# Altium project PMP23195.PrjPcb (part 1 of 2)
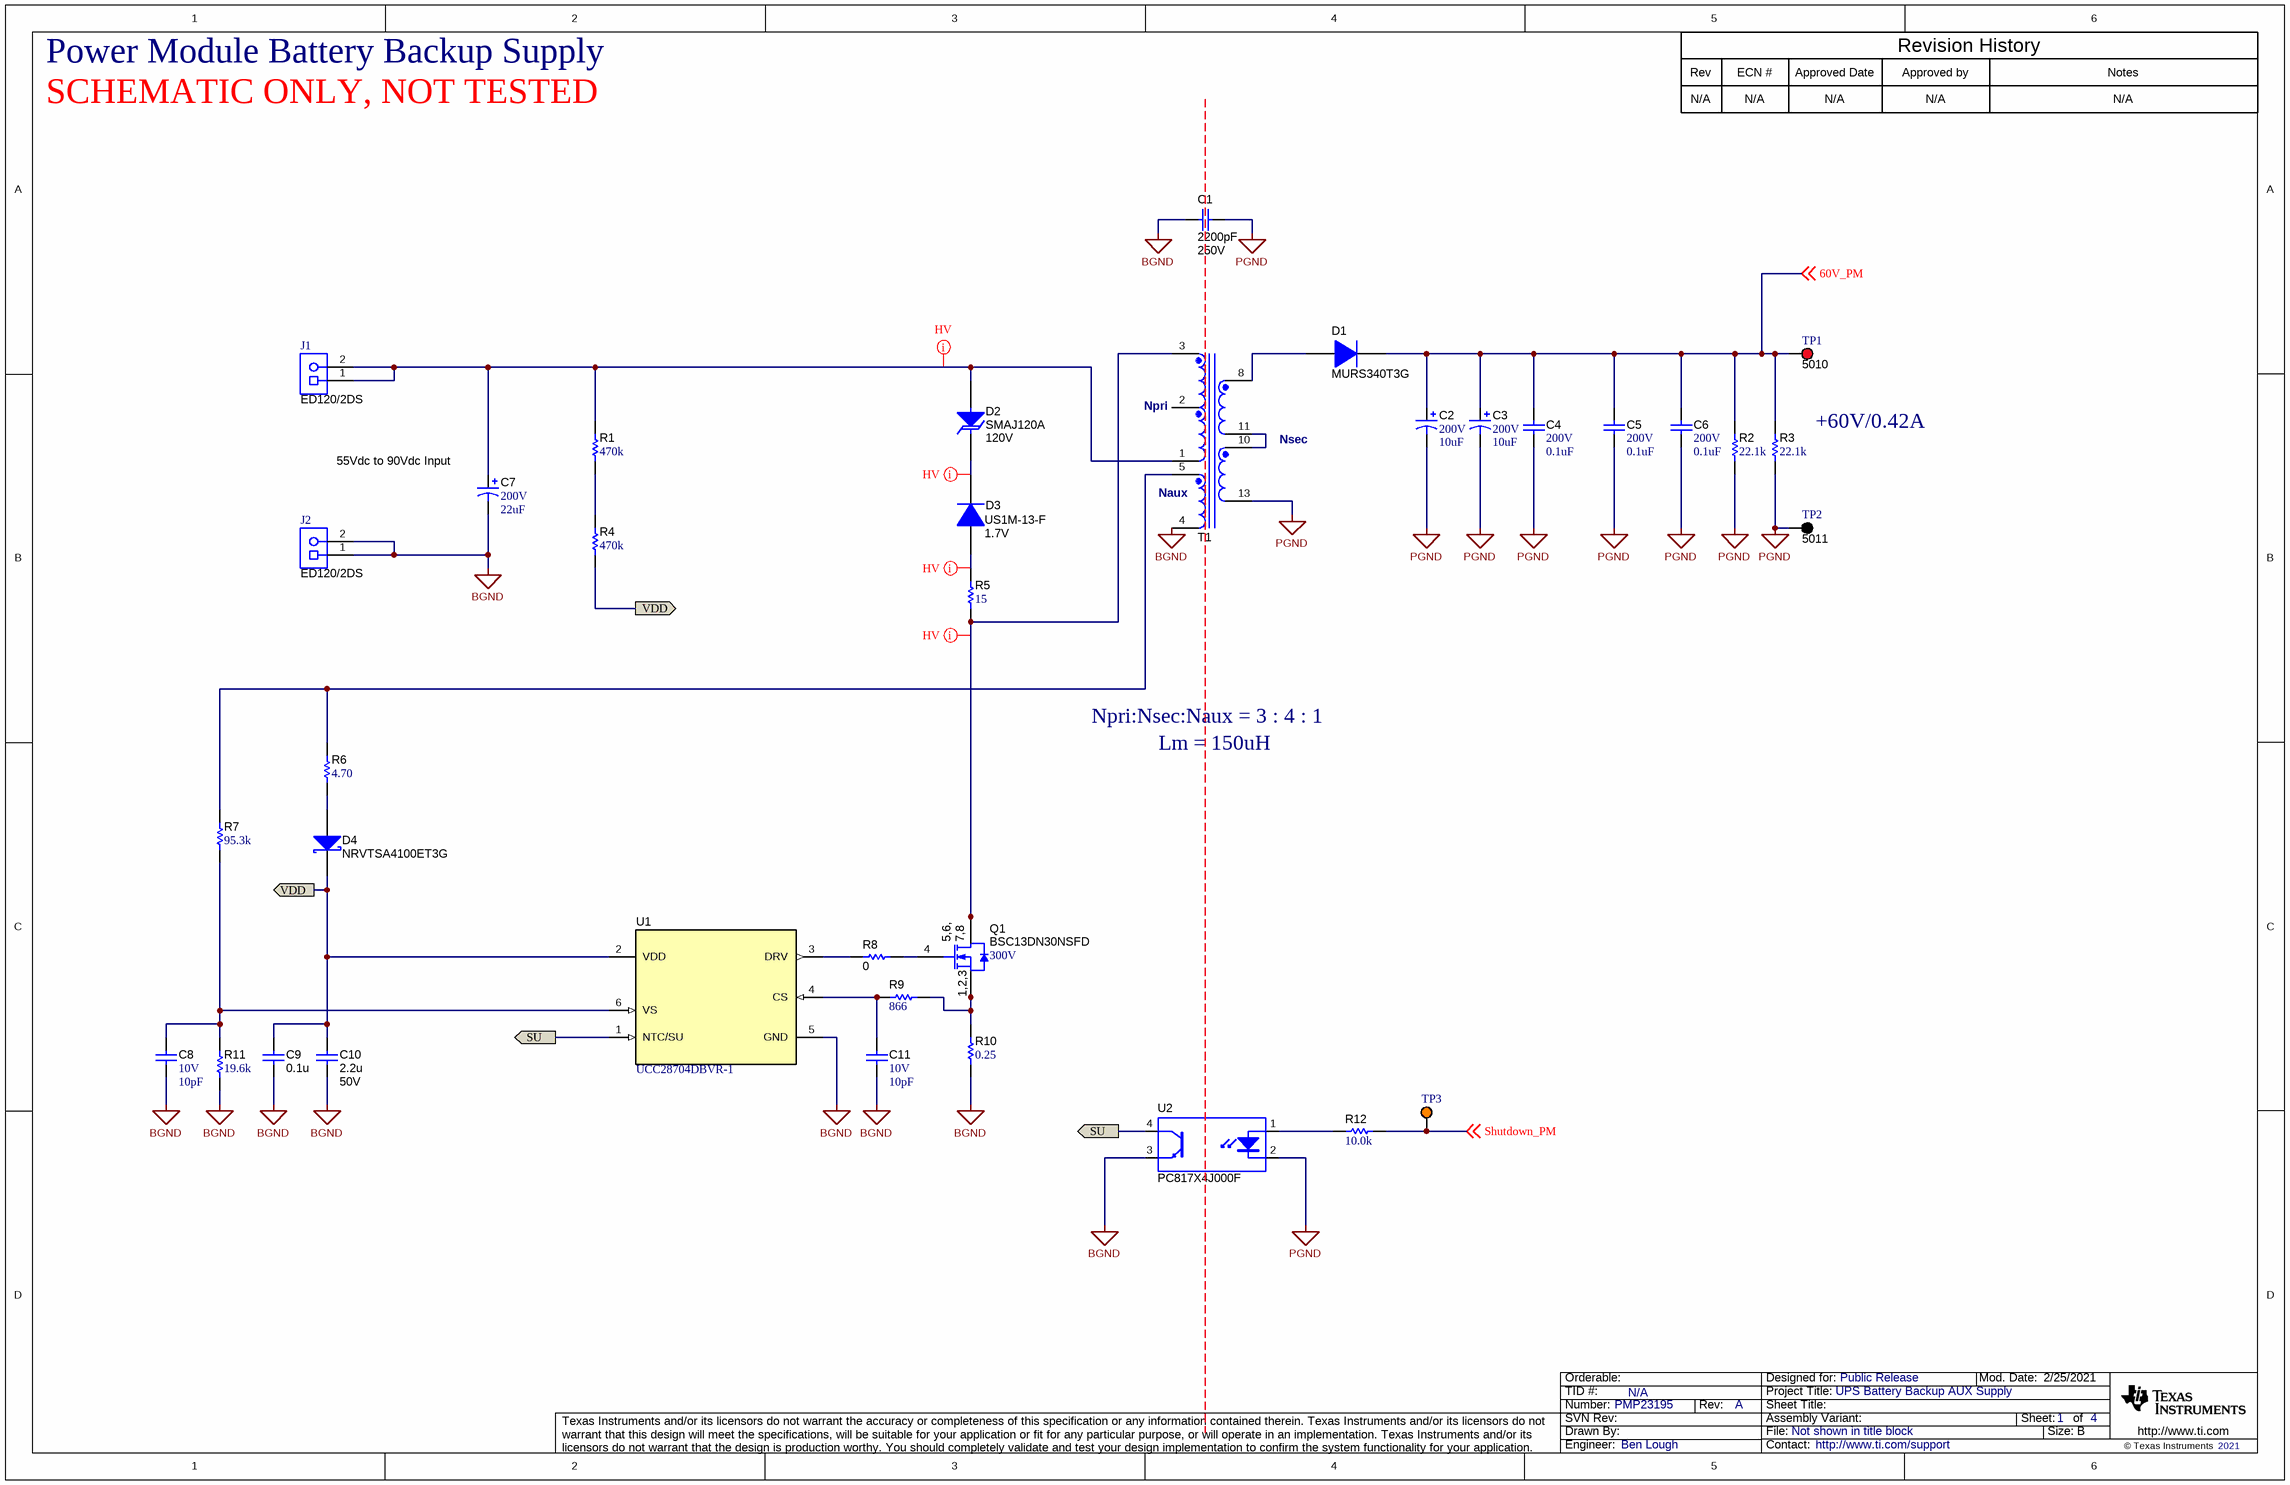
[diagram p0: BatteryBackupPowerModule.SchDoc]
CopyrightYear: 2021; PCB_Layout: N/A; PCB_Rev: A; PRJ_Customer: Public Release; PRJ_Engineer: Ben Lough; PRJ_Number: PMP23195; PRJ_Title: UPS Battery Backup AUX Supply; SCH_Rev: A; TechSupport: http://www.ti.com/support; TID: N/A
4 sheets, 246 parts. Net scope: flat (ports and power ports of the same name join across sheets).
Board file: PMP23195.PcbDoc
Sheets:
  BatteryBackupPowerModule.SchDoc
  PowerModule_ZVS_Flyback.SchDoc
  SystemAUX_ZVSFlyback.SchDoc
  BatteryBackupSystemAUX.SchDoc

## Sheet BatteryBackupPowerModule.SchDoc
size 431 x 279 mm; Date: Not shown in title block; ApprovedBy: Not shown in title block; CheckedBy: Not shown in title block; Author: Not shown in title block; CompanyName: Not shown in title block; Engineer: Not shown in title block; Organization: Not shown in title block; Address1: Not shown in title block; Address2: Not shown in title block; Address3: Not shown in title block; Address4: Not shown in title block; DocumentNumber: 1; Revision: Use project parameter SCH_Rev; SheetNumber: 1; SheetTotal: 4; PageSetup: Record=PageOptions¦CenterHorizontal=True¦CenterVertical=True¦PrintScale=1.00¦XCorrection=1.00¦YCorrection=1.00¦PrintKind=0¦BorderSize=5000000¦LeftOffset=0¦BottomOffset=0¦Orientation=2¦PaperLength=1000¦PaperWidth=1000¦Scale=100¦PaperSource=15¦PrintQuality=600¦MediaType=1¦DitherType=10¦PaperKind=Letter¦PrintScaleMode=1

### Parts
C1  ValueDisplayed: 2200pF  Value2: 250V  [CAPRD750W60D1050H1450]  (hidden comment: CS11-E2GA222MYNS)
C2  VDC_V: 200V  ValueDisplayed: 10uF  [VK_800X1150]  (hidden comment: UVK2D100MPD)
C3  VDC_V: 200V  ValueDisplayed: 10uF  [VK_800X1150]  (hidden comment: UVK2D100MPD)
C4  VDC_V: 200V  ValueDisplayed: 0.1uF  [1206]  (hidden comment: C1206C104K2RACTU)
C5  VDC_V: 200V  ValueDisplayed: 0.1uF  [1206]  (hidden comment: C1206C104K2RACTU)
C6  VDC_V: 200V  ValueDisplayed: 0.1uF  [1206]  (hidden comment: C1206C104K2RACTU)
C7  VDC_V: 200V  ValueDisplayed: 22uF  [UPW_1000x2000]  (hidden comment: UPW2D220MPD1TD)
C8  VDC_V: 10V  ValueDisplayed: 10pF  [0402]  (hidden comment: C0402C100C8GACTU)
C9  ValueDisplayed: 0.1u  [0603]  (hidden comment: 06035C104KAT2A)
C10  ValueDisplayed: 2.2u  Value2: 50V  [1206]  (hidden comment: GRM31CR61H225KA88L)
C11  VDC_V: 10V  ValueDisplayed: 10pF  [0402]  (hidden comment: C0402C100C8GACTU)
D1  MURS340T3G  [SMC]
D2  SMAJ120A  value 120V  [SMA]
D3  US1M-13-F  value 1.7V  [SMA]
D4  NRVTSA4100ET3G  [SMA]
J1  ED120/2DS  [On-Shore_ED120_2DS]
J2  ED120/2DS  [On-Shore_ED120_2DS]
Q1  BSC13DN30NSFD  value 300V  [PG-TDSON-8]
R1  ValueDisplayed: 470k  [1206]  (hidden comment: RC1206FR-07470KL)
R2  ValueDisplayed: 22.1k  [1206]  (hidden comment: RC1206FR-0722K1L)
R3  ValueDisplayed: 22.1k  [1206]  (hidden comment: RC1206FR-0722K1L)
R4  ValueDisplayed: 470k  [1206]  (hidden comment: RC1206FR-07470KL)
R5  ValueDisplayed: 15  [1206]  (hidden comment: CRCW120615R0JNEA)
R6  ValueDisplayed: 4.70  [1206]  (hidden comment: RC1206FR-074R7L)
R7  ValueDisplayed: 95.3k  [0603]  (hidden comment: RC0603FR-0795K3L)
R8  value 0  [0603]  (hidden comment: CRCW06030000Z0EA)
R9  ValueDisplayed: 866  [0603]  (hidden comment: RC0603FR-07866RL)
R10  ValueDisplayed: 0.25  [1206]  (hidden comment: CSR1206FKR250)
R11  ValueDisplayed: 19.6k  [0603]  (hidden comment: RC0603FR-0719K6L)
R12  ValueDisplayed: 10.0k  [0603]  (hidden comment: M55342K12B10E0T)
T1  750314727  [WURTH_750314727]  (value not drawn)
TP1  5010  [Keystone5010]
TP2  5011  [Keystone5011]
TP3  5013  [Keystone5013]  (value not drawn)
U1  UCC28704DBVR-1  [DBV0006A_N]
U2  PC817X4J000F  [DIP762W60P254L460H350Q4B]

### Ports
SU (out), VDD (out)

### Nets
BGND: C1.2 C7.2(-) C8.2 C9.2 C10.2 C11.2 J2.1 J2.2 R10.1 R11.1 T1.4 U1.5(GND) U2.3(E)
PGND: C1.1 C2.2(-) C3.2(-) C4.2 C5.2 C6.2 R2.1 R3.1 T1.13 TP2.1 U2.2(K)
60V_PM: C2.1(+) C3.1(+) C4.1 C5.1 C6.1 D1.1(K) R2.2 R3.2 TP1.1 ; off-sheet 60V_PM
Shutdown_PM: R12.2 TP3.1 ; off-sheet Shutdown_PM
SU: U1.1(NTC/SU) U2.4(C) ; port SU
VDD: C9.1 C10.1 D4.1(K) R4.1 U1.2(VDD) ; port VDD
NetC7_1: C7.1(+) D2.2(A) J1.1 J1.2 R1.2 T1.1
NetC8_1: C8.1 R7.1 R11.2 U1.6(VS)
NetC11_1: C11.1 R9.1 U1.4(CS)
NetD1_2: D1.2(A) T1.8
NetD2_1: D2.1(K) D3.1(K)
NetD3_2: D3.2(A) R5.2
NetD4_2: D4.2(A) R6.1
NetQ1_1: Q1.1(S) Q1.2(S) Q1.3(S) R9.2 R10.2
NetQ1_4: Q1.4(G) R8.2
NetQ1_5: Q1.5(D) Q1.6(D) Q1.7(D) Q1.8(D) Q1.9(D) R5.1 T1.3
NetR1_1: R1.1 R4.2
NetR6_2: R6.2 R7.2 T1.5
NetR8_1: R8.1 U1.3(DRV)
NetR12_1: R12.1 U2.1(A)
NetT1_10: T1.10 T1.11

Not connected (* = marked no-connect by the designer): T1 2

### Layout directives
net class HV: NetC7_1, NetD2_1, NetD3_2, NetQ1_5

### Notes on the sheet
- Power Module Battery Backup Supply
- Rev
- N/A
- ECN #
- Approved Date
- Approved by
- Revision History
- Notes
- SCHEMATIC ONLY, NOT TESTED
- (near T1) Npri
- +60V/0.42A
- (near C7) 55Vdc to 90Vdc Input
- (near T1) Naux
- Nsec
- Npri:Nsec:Naux = 3 : 4 : 1
- Lm = 150uH

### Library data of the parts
C1 = CS11-E2GA222MYNS: CAP, CERM, 2200pF, 250V, +/-20%, E, Radial Disc D10.5x7mm; Manufacturer: TDK; Polarized: N; CompType: Capacitor; U/M: EA; Cap_F: 0.0000000022; Tolerance_%: 20; Value1: Unknown; VDC_V: 250; TaMin_C: -25; TaMax_C: 105; Cap_Case: Disc, 10.5x7mm
C2 C3 = CMP-0064891-1: CAP, AL, 10 uF, 200 V, +/- 20%, TH; Manufacturer: Nichicon; TaMin_C: -40°C; Polarized: Y; SizeAreaWB_mm2: 100; Value1: Unknown; U/M: EA; Value: 10uF; TaMax_C: 85°C; SizeZ_mm: 13; SizeX_mm: 8; Cap_Case: 8x11.5mm; SizeArea_mm2: 64; CompType: Capacitor; AEC Qualified: N; Cap_F: 10µF; IRMS_A: 80mA; AEC Category: Q200
C4-C6 = CMP-0008585-2: CAP, CERM, 0.1 uF, 200 V, +/- 10%, X7R, 1206; Manufacturer: Kemet; TaMin_C: -55°C; Polarized: N; SizeAreaWB_mm2: 10.92; Value1: Unknown; U/M: EA; Value: 0.1uF; TaMax_C: 125°C; SizeZ_mm: 1.35; SizeX_mm: 3.2; SizeY_mm: 1.6; SizeArea_mm2: 5.12; Cap_F: 100nF; AEC Category: Q200
C7 = CMP-0064890-1: CAP, AL, 22 uF, 200 V, +/- 20%, TH; Manufacturer: Nichicon; TaMin_C: -40°C; Polarized: Y; SizeAreaWB_mm2: 144; Value1: Unknown; U/M: EA; Value: 22uF; TaMax_C: 105°C; SizeZ_mm: 22; SizeX_mm: 10; Cap_Case: 10x20mm; SizeArea_mm2: 100; CompType: Capacitor; AEC Qualified: N; Cap_F: 22µF; IRMS_A: 1.4dA; AEC Category: Q200
C8 C11 = CMP-0064914-2: CAP, CERM, 10 pF, 10 V,+/- 2.5%, C0G/NP0, 0402; Manufacturer: Kemet; TaMin_C: -55°C; Polarized: N; SizeAreaWB_mm2: 3; Value1: Unknown; U/M: EA; Value: 10pF; TaMax_C: 125°C; SizeZ_mm: 0.6; SizeX_mm: 1; SizeY_mm: 0.5; AEC Category: Q200
C9 = 06035C104KAT2A: CAP, CERM, 0.1uF, 50V, +/-10%, X7R, 0603; Manufacturer: AVX; Polarized: N; CompType: Capacitor; U/M: EA; Cap_F: 0.0000001; Tolerance_%: 10; Value1: Unknown; VDC_V: 50; TaMin_C: -55; TaMax_C: 125
C10 = GRM31CR61H225KA88L: CAP, CERM, 2.2uF, 50V, +/-10%, X5R, 1206; Manufacturer: MuRata; Polarized: N; CompType: Capacitor; U/M: EA; Cap_F: 0.0000022; Tolerance_%: 10; Value1: Unknown; VDC_V: 50; TaMin_C: -55; TaMax_C: 85
D1 = CMP-0076962-2: Diode, Ultrafast, 400 V, 3 A, SMC; Manufacturer: ON Semiconductor; AEC Category: Q101; Io_A: 3A; RJC_CperW: 11.0; SizeArea_mm2: 50.5686; SizeX_mm: 8.13; SizeZ_mm: 2.6; SizeAreaWB_mm2: 83.2686; TJmax_C: 175°C; Green_REACh: Incomplete; Value2: 1.25V; Vr_V: 400V; Green_Lifecycle: Not Set; SizeY_mm: 6.22; Value: 400V
D2 = SMAJ120A: Diode, TVS, Uni, 120V, 400W, SMA; Manufacturer: Littelfuse; U/M: EA; Power_W: 400; Vr_V: 120
D3 = US1M-13-F: Diode, Ultrafast, 1000V, 1A, SMA; Manufacturer: Diodes Inc.; U/M: EA; Vf_V: 1.7; Io_A: 1; Vr_V: 1000; TJmax_C: 150; RJC_CperW: 30
D4 = CMP-0081057-2: Diode, Schottky, 100 V, 4 A, AEC-Q101, SMA; Manufacturer: ON Semiconductor; SizeZ_mm: 2.87; SizeY_mm: 2.92; SizeAreaWB_mm2: 37.3428; Io_A: 4A; AEC Category: Q101; SizeX_mm: 5.59; Value: 100V; SizeArea_mm2: 16.3228; Value2: 0.68V; TJmax_C: 175°C; AEC Qualified: Y; Vf_V: 680mV
J1 J2 = CMP-0074910-1: Terminal Block, 5.08 mm, 2x1, Brass, TH; Manufacturer: On-Shore Technology; Cert_VDE: Y; CNHeader: False; Current_A: 15A; Green_Lifecycle: Not Set; Shrouded: N; Gender: Female; Green_REACh: Incomplete; Voltage_V: 300V; Row_Count: 1; Pitch_mm: 5.08; CT: True
Q1 = CMP-0000907-1: MOSFET, N-CH, 300 V, 16 A, PG-TDSON-8; Alternate Manufacturer: None; Manufacturer: Infineon Technologies; SizeZ_mm: 1.12; ChType: N; SizeX_mm: 5.99; SizeY_mm: 4.9; Vgs_V: 20V; SizeArea_mm2: 29.351; IdsMax_A: 16A; SizeAreaWB_mm2: 55.131; U/M: EA; QgTyp_nC: 23
R1 R4 = CMP-0018313-2: RES, 470 k, 1%, 0.25 W, 1206; Manufacturer: Yageo America; Power_W: 250mW; TempCo: 100 ppm/C; U/M: EA; Value: 470k; SizeX_mm: 3.2; SizeY_mm: 1.6; SizeZ_mm: 1.35; Value2: 0.25W; SizeArea_mm2: 5.12; VDC_V: 200V; AEC Category: Q200
R2 R3 = CMP-0018082-2: RES, 22.1 k, 1%, 0.25 W, 1206; Manufacturer: Yageo America; Power_W: 250mW; TempCo: 100 ppm/C; Value_Code: 22k1; U/M: EA; Value: 22.1k; EIA_Code: E96; SizeX_mm: 3.2; SizeY_mm: 1.6; SizeZ_mm: 1.35; Value2: 0.25W; SizeArea_mm2: 5.12; VDC_V: 200V; AEC Category: Q200
R5 = CMP-0018594-3: RES, 15, 5%, 0.25 W, AEC-Q200 Grade 0, 1206; Manufacturer: Vishay-Dale; Power_W: 250mW; TempCo: 200 ppm/C; Value_Code: 15R0; Value: 15; EIA_Code: E24; SizeX_mm: 3.2; SizeY_mm: 1.6; SizeZ_mm: 1.35; Value2: 0.25W; SizeArea_mm2: 5.12; AEC Qualified: Y; VDC_V: 200V; AEC Category: Q200; AEC Grade: 0
R6 = CMP-0018350-2: RES, 4.70, 1%, 0.25 W, 1206; Manufacturer: Yageo America; Power_W: 250mW; TempCo: 200 ppm/C; Value_Code: 4R70; U/M: EA; Value: 4.70; Res_ohm: 4.7; SizeX_mm: 3.2; SizeY_mm: 1.6; SizeZ_mm: 1.35; Value2: 0.25W; SizeArea_mm2: 5.12; VDC_V: 200V; AEC Category: Q200
R7 = CMP-0023326-5: RES, 95.3 k, 1%, 0.1 W, 0603; Manufacturer: Yageo; Power_W: 100mW; TempCo: 100 ppm/C; Value_Code: 95k3; Value: 95.3k; EIA_Code: E96; SizeX_mm: 1.6; SizeY_mm: 0.8; SizeZ_mm: 1; Value2: 0.1W; SizeArea_mm2: 1.28; AEC Qualified: N; VDC_V: 75V; AEC Category: Q200; SizeAreaWB_mm2: 4.68
R8 = CRCW06030000Z0EA: RES, 0 ohm, 5%, 0.1W, 0603; Manufacturer: Vishay-Dale; CompType: Resistor; Value_Code: 0000; Tolerance_%: 5; Power_W: 0.1; VDC_V: 75; TempCo: 200 ppm/C; EIA_Code: E24; U/M: EA
R9 = CMP-0023300-5: RES, 866, 1%, 0.1 W, 0603; Manufacturer: Yageo; Power_W: 100mW; TempCo: 100 ppm/C; Value_Code: 866R; Value: 866; EIA_Code: E96; SizeX_mm: 1.6; SizeY_mm: 0.8; SizeZ_mm: 1; Value2: 0.1W; SizeArea_mm2: 1.28; AEC Qualified: N; VDC_V: 75V; AEC Category: Q200; SizeAreaWB_mm2: 4.68
R10 = CMP-0017267-2: RES, 0.25, 1%, 0.5 W, 1206; Manufacturer: Stackpole Electronics Inc; Power_W: 500mW; TempCo: 100 ppm/C; Value_Code: R250; U/M: EA; Value: 0.25; Res_ohm: 2.5d; SizeX_mm: 3.2; SizeY_mm: 1.6; SizeZ_mm: 1.35; Value2: 0.5W; SizeArea_mm2: 5.12; AEC Category: Q200
R11 = CMP-0022861-5: RES, 19.6 k, 1%, 0.1 W, 0603; Manufacturer: Yageo; Power_W: 100mW; TempCo: 100 ppm/C; Value_Code: 19k6; Value: 19.6k; EIA_Code: E96; SizeX_mm: 1.6; SizeY_mm: 0.8; SizeZ_mm: 1; Value2: 0.1W; SizeArea_mm2: 1.28; AEC Qualified: N; VDC_V: 75V; AEC Category: Q200; SizeAreaWB_mm2: 4.68
R12 = CMP-0080488-1: RES, 10.0 k, 1%, 0.1 W, 0603; Manufacturer: TT Electronics/IRC; Power_W: 100mW; TempCo: 100 ppm/C; SizeAreaWB_mm2: 4.68; Value_Code: 10k0; Value: 10.0k; EIA_Code: E96; Res_ohm: 10k; SizeX_mm: 1.6; SizeY_mm: 0.8; SizeZ_mm: 1; Value2: 0.1W; SizeArea_mm2: 1.28; AEC Qualified: N; AEC Category: Q200
T1 = 750314727: Transformer, 80uH, TH; Manufacturer: Wurth Elektronik eiSos; SymbolCreator: x0208325; DCR_Ohm: 0.221; Value: 250uH; LeakageL: TBD; U/M: EA
TP1 = CMP-0055147-2: Test Point, Multipurpose, Red, TH; Manufacturer: Keystone Electronics; CT: TRUE; ContactFinish: Silver; Green_Lifecycle: Active; CNHeader: FALSE; Green_REACh: Passed
TP2 = CMP-0055148-2: Test Point, Multipurpose, Black, TH; Manufacturer: Keystone Electronics; CNHeader: FALSE; ContactFinish: Silver; Green_REACh: Passed; Green_Lifecycle: Active; CT: TRUE
TP3 = CMP-0055150-2: Test Point, Multipurpose, Orange, TH; Manufacturer: Keystone Electronics; CT: TRUE; ContactFinish: Silver; Green_REACh: Passed; CNHeader: FALSE; Green_Lifecycle: Active
U1 = CMP-0074087-1: Off-Line Constant-Voltage Constant-Current Flyback Controller With Primary-Side Regulation (PSR), DBV0006A (SOT-23-6); Alternate PartNumber: UCC28704DBVT-1; Alternate Manufacturer: Texas Instruments; Green_Lifecycle: Active; SizeAreaWB_mm2: 14.82; Green_REACh: Passed; U/M: EA; SizeZ_mm: 1.45; SizeX_mm: 2.8; SizeY_mm: 2.9; SizeArea_mm2: 8.12; CompType: IC
U2 = LTV-817: Opto-Isolator, 1 Channel, TH; CompType: OPTOCOUPLER; U/M: EA

## Sheet PowerModule_ZVS_Flyback.SchDoc
size 431 x 279 mm; Date: Not shown in title block; ApprovedBy: Not shown in title block; CheckedBy: Not shown in title block; Author: Not shown in title block; CompanyName: Not shown in title block; Engineer: Not shown in title block; Organization: Not shown in title block; Address1: Not shown in title block; Address2: Not shown in title block; Address3: Not shown in title block; Address4: Not shown in title block; DocumentNumber: 1; Revision: Use project parameter SCH_Rev; SheetNumber: 2; SheetTotal: 4; PageSetup: Record=PageOptions¦CenterHorizontal=True¦CenterVertical=True¦PrintScale=1.00¦XCorrection=1.00¦YCorrection=1.00¦PrintKind=0¦BorderSize=5000000¦LeftOffset=0¦BottomOffset=0¦Orientation=2¦PaperLength=1000¦PaperWidth=1000¦Scale=100¦PaperSource=15¦PrintQuality=600¦MediaType=1¦DitherType=10¦PaperKind=Letter¦PrintScaleMode=1
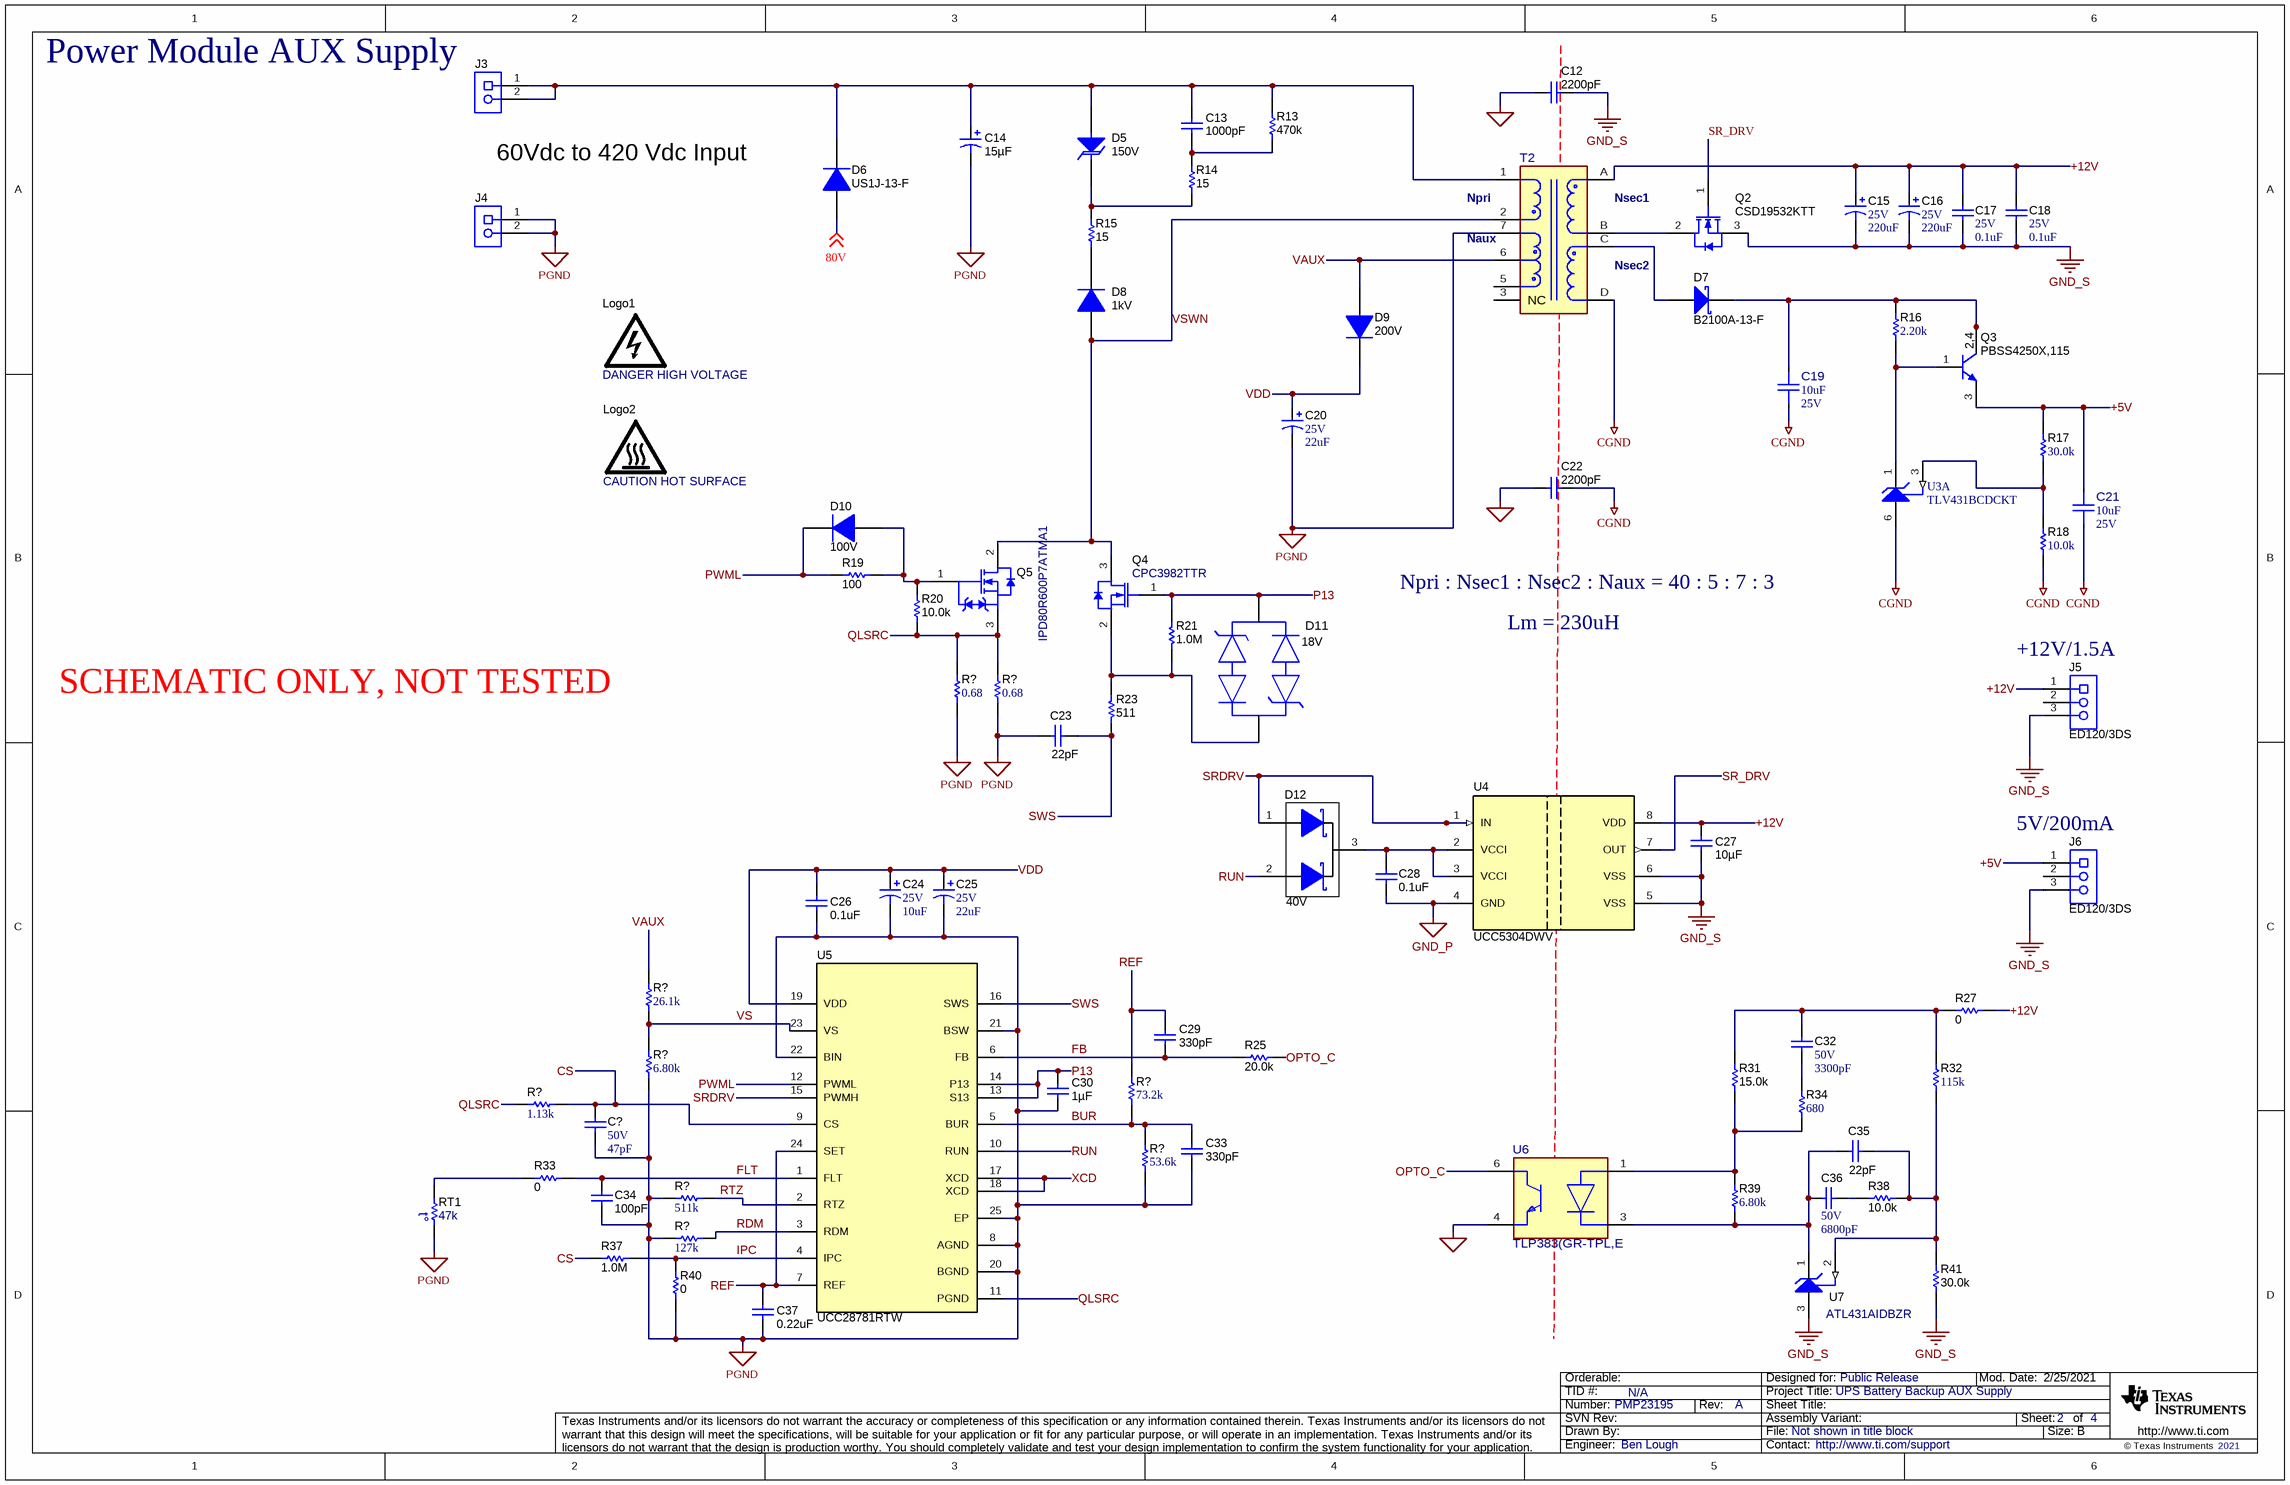
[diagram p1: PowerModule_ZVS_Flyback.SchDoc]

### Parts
(Parts that share a designator on the sheet are numbered #1, #2 ... from top to bottom, then left to right.)
C12  ValueDisplayed: 2200pF  [C900_9x13]  (hidden comment: C921U222MVVDBA7317)
C13  ValueDisplayed: 1000pF  [1206L]  (hidden comment: GRM31BR72J102KW01L)
C14  ValueDisplayed: 15µF  [UVC_1000x1600]  (hidden comment: UVC2G150MPD)
C15  VDC_V: 25V  ValueDisplayed: 220uF  [BT_1000x1250]  (hidden comment: UBT1E221MPD1TD)
C16  VDC_V: 25V  ValueDisplayed: 220uF  [BT_1000x1250]  (hidden comment: UBT1E221MPD1TD)
C17  VDC_V: 25V  ValueDisplayed: 0.1uF  [0603]  (hidden comment: 06033D104KAT2A)
C18  VDC_V: 25V  ValueDisplayed: 0.1uF  [0603]  (hidden comment: 06033D104KAT2A)
C19  ValueDisplayed: 10uF  VDC_V: 25V  [FP-ZRB18AR61E106ME01L_0603-MFG]  (hidden comment: ZRB18AR61E106ME01L)
C20  VDC_V: 25V  ValueDisplayed: 22uF  [SM_RADIAL_D]  (hidden comment: EEE-FC1E220P)
C21  ValueDisplayed: 10uF  VDC_V: 25V  [FP-ZRB18AR61E106ME01L_0603-MFG]  (hidden comment: ZRB18AR61E106ME01L)
C22  ValueDisplayed: 2200pF  [C900_9x13]  (hidden comment: C921U222MVVDBA7317)
C23  ValueDisplayed: 22pF  [0402S]  (hidden comment: GCM1555C1H220JA16D)
C24  VDC_V: 25V  ValueDisplayed: 10uF  [CAPSMT_62_D55]  (hidden comment: EMVA250ADA100MD55G)
C25  VDC_V: 25V  ValueDisplayed: 22uF  [SM_RADIAL_D]  (hidden comment: EEE-FC1E220P)
C26  ValueDisplayed: 0.1uF  [0402S]  (hidden comment: GRM155R71H104ME14D)
C27  ValueDisplayed: 10µF  [1206_180L]  (hidden comment: C1206C106J3RACAUTO)
C28  ValueDisplayed: 0.1uF  [0402S]  (hidden comment: GRM155R71H104ME14D)
C29  ValueDisplayed: 330pF  [0402S]  (hidden comment: GRM155R71H331KA01D)
C30  Cap_F: 1µF  [0603S]  (hidden comment: CGA3E1X7R1V105K080AC)
C32  VDC_V: 50V  ValueDisplayed: 3300pF  [0402]  (hidden comment: GRM155R71H332KA01D)
C33  ValueDisplayed: 330pF  [0402S]  (hidden comment: GRM155R71H331KA01D)
C34  ValueDisplayed: 100pF  [0402S]  (hidden comment: GRM1555C1H101JA01D)
C35  ValueDisplayed: 22pF  [0402S]  (hidden comment: GCM1555C1H220JA16D)
C36  VDC_V: 50V  ValueDisplayed: 6800pF  [0402]  (hidden comment: GRM155R71H682KA88D)
C37  ValueDisplayed: 0.22uF  [0402S]  (hidden comment: GRM155R71C224KA12D)
C?#1  VDC_V: 50V  ValueDisplayed: 47pF  [0402]  (hidden comment: GRM1555C1H470JZ01)
D5  VRWM: 150V  [SMA]  (hidden comment: SMAJ150A)
D6  US1J-13-F  [SMA]
D7  B2100A-13-F  [SMA]
D8  Vr_V: 1kV  [SMA]  (hidden comment: MRA4007T3G)
D9  Vr_V: 200V  [SOD-123H]  (hidden comment: CSFMT104-HF)
D10  Vr_V: 100V  [SOD-323]  (hidden comment: BAS316,115)
D11  CDSOD323-T18C  [FP-CDSOD323-T18C_SOD323-MFG]  (value not drawn)
D12  Vr_V: 40V  [SOT-323]  (hidden comment: BAS40W-05-7-F)
J3  ED120/2DS  [On-Shore_ED120_2DS]  (value not drawn)
J4  ED120/2DS  [On-Shore_ED120_2DS]  (value not drawn)
J5  ED120/3DS  [On-Shore_ED120_3DS]
J6  ED120/3DS  [On-Shore_ED120_3DS]
Logo1  DANGER HIGH VOLTAGE  [IEC_HighVoltage_Small]  (no BOM)
Logo2  CAUTION HOT SURFACE  [IEC_HotSurface_Small]  (no BOM)
Q2  CSD19532KTT  [KTT0002A]
Q3  PBSS4250X,115  [SOT-89-3]
Q4  CPC3982TTR  [SOT-23L]
Q5  IPD80R600P7ATMA1  [DPAK]
R13  ValueDisplayed: 470k  [0805_HV1]  (hidden comment: CRCW0805470KJNEA)
R14  ValueDisplayed: 15  [0805_HV1]  (hidden comment: CRCW080515R0JNEA)
R15  ValueDisplayed: 15  [0805_HV1]  (hidden comment: CRCW080515R0JNEA)
R16  ValueDisplayed: 2.20k  [0603]  (hidden comment: RC0603FR-072K2L)
R17  ValueDisplayed: 30.0k  [0603]  (hidden comment: RC0603FR-0730KL)
R18  ValueDisplayed: 10.0k  [0402]  (hidden comment: ERJ-2RKF1002X)
R19  ValueDisplayed: 100  [0805_HV1]  (hidden comment: CRCW0805100RJNEA)
R20  ValueDisplayed: 10.0k  [0402S]  (hidden comment: CRCW040210K0FKED)
R21  ValueDisplayed: 1.0M  [0402S]  (hidden comment: CRCW04021M00JNED)
R23  ValueDisplayed: 511  [0402S]  (hidden comment: CRCW0402511RFKED)
R25  ValueDisplayed: 20.0k  [0402S]  (hidden comment: CRCW040220K0FKED)
R27  ValueDisplayed: 0  [0402S]  (hidden comment: RC0402JR-070RL)
R31  ValueDisplayed: 15.0k  [0402S]  (hidden comment: CRCW040215K0FKED)
R32  ValueDisplayed: 115k  [0402]  (hidden comment: RC1005F1153CS)
R33  ValueDisplayed: 0  [0402S]  (hidden comment: CRCW04020000Z0EDHP)
R34  ValueDisplayed: 680  [0603]  (hidden comment: RC0603FR-07680RL)
R37  ValueDisplayed: 1.0M  [0402S]  (hidden comment: CRCW04021M00JNED)
R38  ValueDisplayed: 10.0k  [0402S]  (hidden comment: CRCW040210K0FKED)
R39  ValueDisplayed: 6.80k  [0603]  (hidden comment: RC0603FR-076K8L)
R40  ValueDisplayed: 0  [0402S]  (hidden comment: CRCW04020000Z0EDHP)
R41  ValueDisplayed: 30.0k  [0402S]  (hidden comment: CRCW040230K0FKED)
R?#1  ValueDisplayed: 0.68  [1206]  (hidden comment: ERJ-8RQFR68V)
R?#2  ValueDisplayed: 0.68  [1206]  (hidden comment: ERJ-8RQFR68V)
R?#3  ValueDisplayed: 26.1k  [0603]  (hidden comment: RC0603FR-0726K1L)
R?#4  ValueDisplayed: 6.80k  [0402]  (hidden comment: RC0402FR-076K8L)
R?#5  ValueDisplayed: 73.2k  [0402]  (hidden comment: CRCW040273K2FKED)
R?#6  ValueDisplayed: 1.13k  [0402]  (hidden comment: CRCW04021K13FKED)
R?#7  ValueDisplayed: 53.6k  [0402]  (hidden comment: CRCW040253K6FKED)
R?#8  ValueDisplayed: 511k  [0402]  (hidden comment: CRCW0402511KFKED)
R?#9  ValueDisplayed: 127k  [0402]  (hidden comment: CRCW0402127KFKED)
RT1  value 47k  [0603S]  (hidden comment: NCP18WB473J03RB)
T2  RLTI-1324  [FP-RLTI-1324_PTH_0IN980_0IN766-MFG]  (value not drawn)
U3  TLV431BCDCKT  [DCK0006A_N]  (part A of 2)
U4  UCC5304DWV  [DWV0008A]
U5  UCC28781RTW  [RTW0024B]
U6  TLP383(GR-TPL,E  [FP-TLP383(GR-TPL,E_SO6-4-MFG]
U7  ATL431AIDBZR  [DBZ0003A_L]

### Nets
CGND: C19.1 C21.1 C22.1 R18.1 T2.D U3.6(ANODE)
GND2: C12.2 C22.2 U6.4(Emitter)
GND_P: C28.2 U4.4(GND)
GND_S: C12.1 C15.2(-) C16.2(-) C17.2 C18.2 C27.2 J5.3 J6.3 Q2.3(S) R41.2 U4.5(VSS) U4.6(VSS) U7.3(ANODE)
PGND: C14.2(-) C20.2(-) C23.1 C24.2(-) C25.2(-) C26.2 C30.2 C33.2 C34.1 C37.2 C?#1.2 J4.1 J4.2 R40.1 R?#1.1 R?#2.1 R?#4.1 R?#7.1 R?#8.1 R?#9.1 RT1.2 T2.7 U5.8(AGND) U5.20(BGND) U5.21(BSW) U5.22(BIN) U5.25(EP)
80V: D6.2(A) ; off-sheet 80V
+5V: C21.2 J6.1 Q3.3(E) R17.2
+12V: C15.1(+) C16.1(+) C17.1 C18.1 C27.1 J5.1 R27.1 T2.A U4.8(VDD)
BUR: C33.1 R?#5.1 R?#7.2 U5.5(BUR)
CS: C?#1.1 R37.2 R?#6.2 U5.9(CS)
FB: C29.2 R25.1 U5.6(FB)
FLT: C34.2 R33.2 U5.1(FLT)
IPC: R37.1 R40.2 U5.4(IPC)
OPTO_C: R25.2 U6.6(Collector)
P13: C30.1 D11.2 Q4.1(G) R21.2 U5.13(S13) U5.14(P13)
PWML: D10.1(K) R19.1 U5.12(PWML)
QLSRC: Q5.3(S) R20.1 R?#1.2 R?#2.2 R?#6.1 U5.11(PGND)
RDM: R?#9.2 U5.3(RDM)
REF: C29.1 C37.1 R?#5.2 U5.7(REF) U5.24(SET)
RTZ: R?#8.2 U5.2(RTZ)
RUN: D12.2(A) U5.10(RUN)
SR_DRV: Q2.1(G) U4.7(OUT)
SRDRV: D12.1(A) U4.1(IN) U5.15(PWMH)
SWS: C23.2 R23.1 U5.16(SWS)
VAUX: D9.2(A) R?#3.2 T2.6
VDD: C20.1(+) C24.1(+) C25.1(+) C26.1 D9.1(K) U5.19(VDD)
VS: R?#3.1 R?#4.2 U5.23(VS)
VSWN: D8.2(A) Q4.3(D) Q5.2(D) T2.2
XCD: U5.17(XCD) U5.18(XCD)
NetC13_1: C13.1 C14.1(+) D5.2(A) D6.1(K) J3.1 J3.2 R13.2 T2.1
NetC13_2: C13.2 R13.1 R14.2
NetC19_2: C19.2 D7.1(K) Q3.2(C) Q3.4(C) R16.2
NetC28_1: C28.1 D12.3(K) U4.2(VCCI) U4.3(VCCI)
NetC32_1: C32.1 R27.2 R31.2 R32.2
NetC32_2: C32.2 R34.2
NetC35_1: C35.1 C36.2 R39.1 U6.3(Cathode) U7.1(CATHODE)
NetC35_2: C35.2 R32.1 R38.2 R41.1 U7.2(REF)
NetC36_1: C36.1 R38.1
NetD5_1: D5.1(K) R14.1 R15.2
NetD7_2: D7.2(A) T2.C
NetD8_1: D8.1(K) R15.1
NetD10_2: D10.2(A) Q5.1(G) R19.2 R20.2
NetD11_1: D11.1 Q4.2(S) R21.1 R23.2
NetQ2_2: Q2.2(D) T2.B
NetQ3_1: Q3.1(B) R16.1 U3.1(CATHODE)
NetR17_1: R17.1 R18.2 U3.3(REF)
NetR31_1: R31.1 R34.1 R39.2 U6.1(Anode)
NetR33_1: R33.1 RT1.1

Not connected (* = marked no-connect by the designer): J5 2; J6 2; T2 3(NC) 5

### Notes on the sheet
- (near J3) Power Module AUX Supply
- 60Vdc to 420 Vdc Input
- (near T2) Npri
- (near T2) Nsec1
- (near T2) Naux
- (near T2) Nsec2
- Npri : Nsec1 : Nsec2 : Naux = 40 : 5 : 7 : 3
- Lm = 230uH
- SCHEMATIC ONLY, NOT TESTED
- (near D11) 18V
- (near J5) +12V/1.5A
- (near J6) 5V/200mA

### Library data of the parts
C12 C22 = CMP-0078358-1: CAP, CERM, 2200 pF, X1 400 VAC/Y1 400 VAC, +/- 20%, Y5V, D9xL13mm; Manufacturer: Kemet; Cap_F: 2.2nF; SizeAreaWB_mm2: 121; VAC_X: 400V; SizeArea_mm2: 81; AEC Qualified: N; AEC Category: Q200; Value: 2200pF; TaMax_C: 125°C; SizeZ_mm: 13; TaMin_C: -40°C; SizeY_mm: 9; U/M: EA; AC_Safety: X1Y1; Cap_Case: 9x13mm
C13 = CMP-0008909-2: CAP, CERM, 1000 pF, 630 V, +/- 10%, X7R, 1206; Manufacturer: MuRata; TaMin_C: -55°C; Polarized: N; SizeAreaWB_mm2: 10.92; Value1: Unknown; U/M: EA; Value: 1000pF; TaMax_C: 125°C; SizeZ_mm: 1.35; SizeX_mm: 3.2; SizeY_mm: 1.6; Cap_Case: 1206; Value2: 630V; SizeArea_mm2: 5.12; Cap_F: 1nF; AEC Category: Q200
C14 = CMP-0860955-2: CAP, AL, 15 µF, 400 V, +/- 20%, AEC-Q200 Grade 2, TH; Manufacturer: Nichicon; SizeArea_mm2: 100; CompType: Capacitor; Value2: 400V; SizeZ_mm: 18; IRMS_A: 180mA; Polarized: Y; SizeX_mm: 10; Value: 15uF; TaMin_C: -40°C; AEC Grade: 2; U/M: EA; SizeAreaWB_mm2: 144; Cap_Case: 10x16; TaMax_C: 105°C; AEC Category: Q200
C15 C16 = CMP-0010527-1: CAP, AL, 220 uF, 25 V, +/- 20%, 0.1 ohm, TH; Manufacturer: Nichicon; TaMin_C: -40°C; ESR_ohm: 1d; Polarized: Y; SizeAreaWB_mm2: 144; Value1: 0.1 ohm; U/M: EA; Value: 220uF; TaMax_C: 125°C; SizeZ_mm: 14.5; SizeX_mm: 10; Cap_Case: 10x12.5mm; SizeArea_mm2: 100; CompType: Capacitor; Cap_F: 220µF; IRMS_A: 6.8dA; AEC Category: Q200
C17 C18 = CMP-0006758-5: CAP, CERM, 0.1 uF, 25 V, +/- 10%, X5R, 0603; Manufacturer: AVX; TaMin_C: -55°C; ESR_ohm: 0.048; Polarized: N; SizeAreaWB_mm2: 4.68; Value1: 0.048 ohm; U/M: EA; Value: 0.1uF; TaMax_C: 85°C; SizeZ_mm: 1; SizeX_mm: 1.6; SizeY_mm: 0.8; SizeArea_mm2: 1.28; Cap_F: 100nF; IRMS_A: 5.3dA; AEC Category: Q200
C19 C21 = CMP-0094458-1: 10µF ±20% 25V Ceramic Capacitor X5R 0603 (1608 Metric); Manufacturer: Murata Electronics; SizeZ_mm: 1.2mm; AEC Qualified: No
C20 C25 = CMP-0010654-1: CAP, AL, 22 uF, 25 V, +/- 20%, 1 ohm, SMD; Manufacturer: Panasonic; TaMin_C: -40°C; ESR_ohm: 1; Polarized: Y; SizeAreaWB_mm2: 84.28; Value1: 1 ohm; U/M: EA; Value: 22uF; TaMax_C: 105°C; SizeZ_mm: 5.4; SizeX_mm: 7.8; SizeY_mm: 6.6; Cap_Case: D; SizeArea_mm2: 51.48; CompType: Capacitor; Cap_F: 22µF; IRMS_A: 1.15dA; AEC Category: Q200
C23 C35 = CMP-0006348-2: CAP, CERM, 22 pF, 50 V, +/- 5%, C0G/NP0, AEC-Q200 Grade 1, 0402; Manufacturer: MuRata; TaMin_C: -55°C; Polarized: N; SizeAreaWB_mm2: 3; Value1: Unknown; U/M: EA; Value: 22pF; TaMax_C: 125°C; SizeZ_mm: 0.6; SizeX_mm: 1; SizeY_mm: 0.5; Cap_Case: 0402; Value2: 50V; AEC Qualified: Y; AEC Category: Q200
C24 = CMP-0010785-1: CAP, AL, 10 uF, 25 V, +/- 20%, SMD; Manufacturer: Chemi-Con; TaMin_C: -40°C; Polarized: Y; SizeAreaWB_mm2: 28.09; Value1: Unknown; U/M: EA; Value: 10uF; TaMax_C: 85°C; SizeZ_mm: 5.2; SizeX_mm: 4.3; Cap_Case: D55; SizeArea_mm2: 18.49; CompType: Capacitor; Cap_F: 10µF; IRMS_A: 24mA; AEC Category: Q200
C26 C28 = CMP-0006675-2: CAP, CERM, 0.1 uF, 50 V, +/- 20%, X7R, 0402; Manufacturer: MuRata; TaMin_C: -55°C; Polarized: N; SizeAreaWB_mm2: 3; Value1: Unknown; U/M: EA; Value: 0.1uF; TaMax_C: 125°C; SizeZ_mm: 0.6; SizeX_mm: 1; SizeY_mm: 0.5; Cap_Case: 0402; Value2: 50V; Cap_F: 100nF; AEC Category: Q200
C27 = CMP-0081062-1: CAP, CERM, 10 µF, 25 V,+/- 5%, X7R, AEC-Q200 Grade 1, 1206; Manufacturer: Kemet; TaMin_C: -55°C; Polarized: N; SizeAreaWB_mm2: 10.92; U/M: EA; Value: 10uF; TaMax_C: 125°C; SizeZ_mm: 1.8; SizeX_mm: 3.2; SizeY_mm: 1.6; Cap_Case: 1206_180; Value2: 25V; SizeArea_mm2: 5.12; AEC Qualified: Y; AEC Grade: 1; AEC Category: Q200
C29 C33 = CMP-0006687-2: CAP, CERM, 330 pF, 50 V, +/- 10%, X7R, 0402; Manufacturer: MuRata; TaMin_C: -55°C; Polarized: N; SizeAreaWB_mm2: 3; Value1: Unknown; U/M: EA; Value: 330pF; TaMax_C: 125°C; SizeZ_mm: 0.6; SizeX_mm: 1; SizeY_mm: 0.5; Cap_Case: 0402; Value2: 50V; AEC Category: Q200
C30 = CMP-0007067-4: CAP, CERM, 1 uF, 35 V, +/- 10%, X7R, AEC-Q200 Grade 1, 0603; Manufacturer: TDK; TaMin_C: -55°C; ESR_ohm: 5.522m; Polarized: N; SizeAreaWB_mm2: 4.68; Value1: 0.005522 ohm; U/M: EA; Value: 1uF; TaMax_C: 125°C; SizeZ_mm: 1; SizeX_mm: 1.6; SizeY_mm: 0.8; Cap_Case: 0603; Value2: 35V; SizeArea_mm2: 1.28; AEC Qualified: Y; IRMS_A: 2.21617A; AEC Category: Q200
C32 = CMP-0006688-2: CAP, CERM, 3300 pF, 50 V, +/- 10%, X7R, 0402; Manufacturer: MuRata; TaMin_C: -55°C; Polarized: N; SizeAreaWB_mm2: 3; Value1: Unknown; U/M: EA; Value: 3300pF; TaMax_C: 125°C; SizeZ_mm: 0.6; SizeX_mm: 1; SizeY_mm: 0.5; Cap_F: 3.3nF; AEC Category: Q200
C34 = CMP-0006410-2: CAP, CERM, 100 pF, 50 V, +/- 5%, C0G/NP0, 0402; Manufacturer: MuRata; TaMin_C: -55°C; Polarized: N; SizeAreaWB_mm2: 3; Value1: Unknown; U/M: EA; Value: 100pF; TaMax_C: 125°C; SizeZ_mm: 0.6; SizeX_mm: 1; SizeY_mm: 0.5; Cap_Case: 0402; Value2: 50V; AEC Category: Q200
C36 = CMP-0006696-2: CAP, CERM, 6800 pF, 50 V, +/- 10%, X7R, 0402; Manufacturer: MuRata; TaMin_C: -55°C; Polarized: N; SizeAreaWB_mm2: 3; Value1: Unknown; U/M: EA; Value: 6800pF; TaMax_C: 125°C; SizeZ_mm: 0.6; SizeX_mm: 1; SizeY_mm: 0.5; Cap_F: 6.8nF; AEC Category: Q200
C37 = CMP-0006648-2: CAP, CERM, 0.22 uF, 16 V, +/- 10%, X7R, 0402; Manufacturer: MuRata; TaMin_C: -55°C; Polarized: N; SizeAreaWB_mm2: 3; Value1: Unknown; U/M: EA; Value: 0.22uF; TaMax_C: 125°C; SizeZ_mm: 0.6; SizeX_mm: 1; SizeY_mm: 0.5; Cap_Case: 0402; Value2: 16V; Cap_F: 220nF; AEC Category: Q200
C?#1 = CMP-0006469-2: CAP, CERM, 47 pF, 50 V, +/- 5%, C0G/NP0, 0402; Manufacturer: MuRata; TaMin_C: -55°C; ESR_ohm: 0.045; Polarized: N; SizeAreaWB_mm2: 3; Value1: 0.045 ohm; U/M: EA; Value: 47pF; TaMax_C: 125°C; SizeZ_mm: 0.6; SizeX_mm: 1; SizeY_mm: 0.5; AEC Category: Q200
D5 = CMP-0084982-1: Diode, TVS, Uni, 150 V, 243 Vc, 400 W, 1.6 A, SMA; Manufacturer: Littelfuse; Vc: 243V; Ipp: 1.6A; RJA_CperW: 120; AEC Qualified: N; Value: 150V; Ppk: 400W; AEC Category: Q101; SizeArea_mm2: 16.3228; SizeAreaWB_mm2: 37.3428; SizeZ_mm: 2.87; Vbr_Max: 185V; SizeX_mm: 5.59; SizeY_mm: 2.92; Vbr_Min: 167V
D6 = CMP-0077027-2: Diode, Ultrafast, 600 V, 1 A, SMA; Manufacturer: Diodes Inc.; Value: 600V; TJmax_C: 150°C; Value1: 1A; Value2: 1.7V; SizeY_mm: 2.92; Green_REACh: Passed; Green_Lifecycle: Active; SizeX_mm: 5.59; AEC Category: Q101; SizeAreaWB_mm2: 37.3428; SizeZ_mm: 2.87; SizeArea_mm2: 16.3228
D7 = CMP-0081099-2: Diode, Schottky, 100 V, 2 A, SMA; Manufacturer: Diodes Inc.; SizeZ_mm: 2.87; SizeX_mm: 5.59; AEC Qualified: N; Value2: 0.79V; SizeArea_mm2: 16.3228; Vf_V: 790mV; AEC Category: Q101; TJmax_C: 125°C; Vr_V: 100V; Value: 100V; Io_A: 2A; SizeAreaWB_mm2: 37.3428; SizeY_mm: 2.92
D8 = CMP-0077082-2: Diode, Standard Recovery Rectifier, 1000 V, 1 A, AEC-Q101, SMA; Manufacturer: ON Semiconductor; SizeAreaWB_mm2: 37.3428; SizeArea_mm2: 16.3228; AEC Qualified: Y; TJmax_C: 175°C; AEC Category: Q101; Value: 1000V; SizeZ_mm: 2.87; Green_REACh: Passed; Io_A: 1A; Vf_V: 1.1V; SizeY_mm: 2.92; Green_Lifecycle: Active; SizeX_mm: 5.59; RJC_CperW: 16.2
D9 = CMP-0029199-2: Diode, Superfast Rectifier, 200 V, 1 A, 3.5x1.6mm; Manufacturer: Comchip Technology; Vf_V: 950mV; Value: 200V; Value1: 1A; Value2: 0.95V; TJmax_C: 150°C; SizeAreaWB_mm2: 11.7; SizeArea_mm2: 5.6; SizeX_mm: 3.5; SizeY_mm: 1.6; SizeZ_mm: 1; AEC Category: Q101; AEC Qualified: N
D10 = CMP-0029006-2: Diode, Ultrafast, 100 V, 0.25 A, SOD-323; Manufacturer: Nexperia; SizeY_mm: 1.35; Value1: 0.25A; SizeAreaWB_mm2: 8.695; SizeZ_mm: 1; Io_A: 250mA; Value2: 1.4V; SizeX_mm: 2.7; Green_REACh: Incomplete; TJmax_C: 150°C; Green_Lifecycle: Not Set; AEC Category: Q101; Value: 100V; SizeArea_mm2: 3.645
D11 = CMP-0087587-1: Diode, TVS, Bi, 18 V, SOD-323; Manufacturer: Bourns Inc.; SizeZ_mm: 1.14mm; AEC Qualified: No
D12 = CMP-0028437-2: Diode, Schottky, 40 V, 0.2 A, SOT-323; Manufacturer: Diodes Inc.; Io_A: 200mA; Green_Lifecycle: Not Set; SizeAreaWB_mm2: 10.24; Green_REACh: Incomplete; Value1: 0.2A; Value: 40V; SizeZ_mm: 1.1; SizeX_mm: 2.2; Vf_V: 800mV; Value2: 0.8V; SizeArea_mm2: 4.84; AEC Category: Q101
J3 J4 = CMP-0074910-1: Terminal Block, 5.08 mm, 2x1, Brass, TH; Manufacturer: On-Shore Technology; Pitch_mm: 5.08; Gender: Female; Shrouded: N; Row_Count: 1; Current_A: 15A; Voltage_V: 300V; Cert_CULUS: Y; CNHeader: False; CT: True; Green_Lifecycle: Not Set; Green_REACh: Incomplete
J5 J6 = CMP-0074911-1: Terminal Block, 5.08 mm, 3x1, Brass, TH; Manufacturer: On-Shore Technology; Cert_VDE: Y; CNHeader: False; Current_A: 15A; Green_Lifecycle: Not Set; Shrouded: N; Gender: Female; Green_REACh: Incomplete; Voltage_V: 300V; Row_Count: 1; Pitch_mm: 5.08; CT: True
Logo1 = CMP-0074835-1: IEC 61010-1 High Voltage Warning; SymbolCreator: a0412235
Logo2 = CMP-0074837-1: IEC 61010-1 Hot Surface Warning; SymbolCreator: a0412235
Q2 = CMP-0000957-3: MOSFET, N-CH, 100 V, 136 A, KTT0002A (TO-263-2); Alternate Manufacturer: None; Manufacturer: Texas Instruments; SizeZ_mm: 4.7; ChType: N; Value2: 44 nC; VdsMax_V: 100V; SizeX_mm: 14.3; SizeAreaWB_mm2: 198.208; SizeY_mm: 10.16; Vgs_V: 20V; QgTyp_nC: 44; Value: 100V; SizeArea_mm2: 145.288; AEC Category: Q101; IdsMax_A: 136A
Q3 = CMP-0000491-2: Transistor, NPN, 50 V, 2 A, SOT-89; Manufacturer: NXP Semiconductor; TaMax_C: 150°C; Value1: 2 A; Vcesat1_V: 2.5dV; SizeX_mm: 4.1; SizeY_mm: 4.5; TaMin_C: -65°C; IcRated_A: 2A; CompType: BJT; SizeZ_mm: 1.5; AEC Qualified: N; Value: 50 V; SizeArea_mm2: 18.45; NPN: 1; Vceo_V: 50V; PNP: 0; AEC Category: Q101; SizeAreaWB_mm2: 28.05; U/M: EA
Q4 = CMP-0081263-2: MOSFET, N-CH, Depletion Mode, 800 V, SOT-23; Alternate Manufacturer: None; Manufacturer: IXYS; SizeAreaWB_mm2: 14; Vgs_V: 15V; Value1: ? ohm; VdsMax_V: 800V; Value: 800V; SizeZ_mm: 1.1; SizeX_mm: 2.5; SizeY_mm: 3; Value2: ? nC; SizeArea_mm2: 7.5; ChType: N; AEC Category: Q101
Q5 = CMP-0083711-2: MOSFET, N-CH, 800 V, 8 A, DPAK; Manufacturer: Infineon Technologies; Alternate Manufacturer: None; AEC Qualified: N; Vgs_V: 20V; SizeY_mm: 6.54; VdsMax_V: 800V; IdsMax_A: 8A; SizeX_mm: 9.91; Value2: 20 nC; AEC Category: Q101; ChMode: Enhancement; SizeAreaWB_mm2: 101.7114; Value1: ? ohm; SizeArea_mm2: 64.8114; Value: 800V; SizeZ_mm: 2.29; QgTyp_nC: 20
R13 = CMP-0020554-3: RES, 470 k, 5%, 0.125 W, AEC-Q200 Grade 0, 0805; Manufacturer: Vishay-Dale; Power_W: 125mW; TempCo: 200 ppm/C; Value: 470k; EIA_Code: E24; SizeX_mm: 2; SizeY_mm: 1.25; SizeZ_mm: 1.45; Value2: 0.125W; SizeArea_mm2: 2.5; AEC Qualified: Y; VDC_V: 150V; AEC Category: Q200; AEC Grade: 0
R14 R15 = CMP-0020464-3: RES, 15, 5%, 0.125 W, AEC-Q200 Grade 0, 0805; Manufacturer: Vishay-Dale; Power_W: 125mW; TempCo: 200 ppm/C; Value_Code: 15R0; Value: 15; EIA_Code: E24; SizeX_mm: 2; SizeY_mm: 1.25; SizeZ_mm: 1.45; Value2: 0.125W; SizeArea_mm2: 2.5; AEC Qualified: Y; VDC_V: 150V; AEC Category: Q200; AEC Grade: 0
R16 = CMP-0022986-5: RES, 2.20 k, 1%, 0.1 W, 0603; Manufacturer: Yageo; Power_W: 100mW; TempCo: 100 ppm/C; Value_Code: 2k20; Value: 2.20k; Res_ohm: 2.2k; SizeX_mm: 1.6; SizeY_mm: 0.8; SizeZ_mm: 1; Value2: 0.1W; SizeArea_mm2: 1.28; AEC Qualified: N; VDC_V: 75V; AEC Category: Q200; SizeAreaWB_mm2: 4.68
R17 = CMP-0023020-5: RES, 30.0 k, 1%, 0.1 W, 0603; Manufacturer: Yageo; Power_W: 100mW; TempCo: 100 ppm/C; Value_Code: 30k0; Value: 30.0k; Res_ohm: 30k; SizeX_mm: 1.6; SizeY_mm: 0.8; SizeZ_mm: 1; Value2: 0.1W; SizeArea_mm2: 1.28; AEC Qualified: N; VDC_V: 75V; AEC Category: Q200; SizeAreaWB_mm2: 4.68
R18 = CMP-0026658-1: RES, 10.0 k, 1%, 0.1 W, 0402; Manufacturer: Panasonic; Power_W: 100mW; TempCo: 100 ppm/C; Value_Code: 10k0; U/M: EA; Value: 10.0k; EIA_Code: E96; Res_ohm: 10k; SizeX_mm: 1; SizeY_mm: 0.5; SizeZ_mm: 0.6; Value2: 0.1W; VDC_V: 50V; AEC Category: Q200
R19 = CMP-0020445-3: RES, 100, 5%, 0.125 W, AEC-Q200 Grade 0, 0805; Manufacturer: Vishay-Dale; Power_W: 125mW; TempCo: 200 ppm/C; Value_Code: 100R; Value: 100; EIA_Code: E24; SizeX_mm: 2; SizeY_mm: 1.25; SizeZ_mm: 1.45; Value2: 0.125W; SizeArea_mm2: 2.5; AEC Qualified: Y; VDC_V: 150V; AEC Category: Q200; AEC Grade: 0
R20 R38 = CMP-0025958-3: RES, 10.0 k, 1%, 0.063 W, AEC-Q200 Grade 0, 0402; Manufacturer: Vishay-Dale; Power_W: 63mW; TempCo: 100 ppm/C; Value_Code: 10k0; Value: 10.0k; EIA_Code: E96; Res_ohm: 10k; SizeX_mm: 1; SizeY_mm: 0.5; SizeZ_mm: 0.6; Value2: 0.063W; AEC Qualified: Y; VDC_V: 50V; AEC Category: Q200; AEC Grade: 0
R21 = CMP-0026859-2: RES, 1.0 M, 5%, 0.063 W, AEC-Q200 Grade 0, 0402; Manufacturer: Vishay-Dale; Value: 1.0Meg; Res_ohm: 1M; Value_Code: 1M00; Power_W: 63mW; Value2: 0.063W; VDC_V: 50V; TempCo: 200 ppm/C; SizeArea_mm2: 0.5; SizeX_mm: 1; SizeZ_mm: 0.6; EIA_Code: E24; AEC Category: Q200; AEC Qualified: Y; AEC Grade: 0
R23 = CMP-0026436-2: RES, 511, 1%, 0.063 W, AEC-Q200 Grade 0, 0402; Manufacturer: Vishay-Dale; Power_W: 63mW; TempCo: 100 ppm/C; Value_Code: 511R; Value: 511; EIA_Code: E96; SizeX_mm: 1; SizeY_mm: 0.5; SizeZ_mm: 0.6; Value2: 0.063W; AEC Qualified: Y; VDC_V: 50V; AEC Category: Q200; AEC Grade: 0
R25 = CMP-0026162-2: RES, 20.0 k, 1%, 0.063 W, AEC-Q200 Grade 0, 0402; Manufacturer: Vishay-Dale; Power_W: 63mW; TempCo: 100 ppm/C; Value_Code: 20k0; Value: 20.0k; EIA_Code: E96; Res_ohm: 20k; SizeX_mm: 1; SizeY_mm: 0.5; SizeZ_mm: 0.6; Value2: 0.063W; AEC Qualified: Y; VDC_V: 50V; AEC Category: Q200; AEC Grade: 0
R27 = CMP-0027004-2: RES, 0, 5%, 0.063 W, 0402; Manufacturer: Yageo America; Power_W: 63mW; TempCo: 200 ppm/C; Value_Code: 0000; U/M: EA; Value: 0; EIA_Code: E24; SizeX_mm: 1; SizeY_mm: 0.5; SizeZ_mm: 0.6; Value2: 0.063W; VDC_V: 50V; AEC Category: Q200
R31 = CMP-0026027-3: RES, 15.0 k, 1%, 0.063 W, AEC-Q200 Grade 0, 0402; Manufacturer: Vishay-Dale; Power_W: 63mW; TempCo: 100 ppm/C; Value_Code: 15k0; Value: 15.0k; EIA_Code: E96; Res_ohm: 15k; SizeX_mm: 1; SizeY_mm: 0.5; SizeZ_mm: 0.6; Value2: 0.063W; AEC Qualified: Y; VDC_V: 50V; AEC Category: Q200; AEC Grade: 0
R32 = CMP-0077547-1: RES, 115 k, 1%, 0.0625 W, 0402; Manufacturer: Samsung Electro-Mechanics; Power_W: 62.5mW; TempCo: 300 ppm/C; U/M: EA; Value: 115k; EIA_Code: E96; SizeX_mm: 1.0; SizeY_mm: 0.5; SizeZ_mm: 0.6; AEC Qualified: N; VDC_V: 50V; AEC Category: Q200
R33 R40 = CMP-0081856-1: RES, 0, 0%, 0.2 W, AEC-Q200 Grade 0, 0402; Manufacturer: Vishay-Dale; SizeAreaWB_mm2: 3; SizeArea_mm2: 0.5; AEC Qualified: Y; AEC Category: Q200; Value: 0; SizeZ_mm: 0.6; Power_W: 200mW; VDC_V: 50V; Value2: 0.2W; SizeX_mm: 1
R34 = CMP-0023235-5: RES, 680, 1%, 0.1 W, 0603; Manufacturer: Yageo; Power_W: 100mW; TempCo: 100 ppm/C; Value_Code: 680R; Value: 680; SizeX_mm: 1.6; SizeY_mm: 0.8; SizeZ_mm: 1; Value2: 0.1W; SizeArea_mm2: 1.28; AEC Qualified: N; VDC_V: 75V; AEC Category: Q200; SizeAreaWB_mm2: 4.68
R37 = CMP-0026859-2: RES, 1.0 M, 5%, 0.063 W, AEC-Q200 Grade 0, 0402; Manufacturer: Vishay-Dale; Power_W: 63mW; TempCo: 200 ppm/C; Value_Code: 1M00; Value: 1.0Meg; EIA_Code: E24; Res_ohm: 1M; SizeX_mm: 1; SizeY_mm: 0.5; SizeZ_mm: 0.6; Value2: 0.063W; AEC Qualified: Y; VDC_V: 50V; AEC Category: Q200; AEC Grade: 0
R39 = CMP-0023253-5: RES, 6.80 k, 1%, 0.1 W, 0603; Manufacturer: Yageo; Power_W: 100mW; TempCo: 100 ppm/C; Value_Code: 6k80; Value: 6.80k; Res_ohm: 6.8k; SizeX_mm: 1.6; SizeY_mm: 0.8; SizeZ_mm: 1; Value2: 0.1W; SizeArea_mm2: 1.28; AEC Qualified: N; VDC_V: 75V; AEC Category: Q200; SizeAreaWB_mm2: 4.68
R41 = CMP-0078244-2: RES, 30.0 k, 1%, 0.063 W, AEC-Q200 Grade 0, 0402; Manufacturer: Vishay-Dale; Power_W: 63mW; Green_Lifecycle: Active; TempCo: 100 ppm/C; Value_Code: 30k0; Green_REACh: Passed; Value: 30.0k; Res_ohm: 30k; SizeX_mm: 1; SizeY_mm: 0.5; SizeZ_mm: 0.6; Value2: 0.063W; AEC Qualified: Y; VDC_V: 50V; AEC Grade: 0; AEC Category: Q200
R?#1 R?#2 = CMP-0017793-3: RES, 0.68, 1%, 0.25 W, AEC-Q200 Grade 0, 1206; Manufacturer: Panasonic; Power_W: 250mW; TempCo: 250 ppm/C; Value_Code: R680; Value: 0.68; EIA_Code: E96; SizeX_mm: 3.2; SizeY_mm: 1.6; SizeZ_mm: 1.35; Value2: 0.25W; SizeArea_mm2: 5.12; AEC Qualified: Y; AEC Category: Q200; AEC Grade: 0; SizeAreaWB_mm2: 10.92
R?#3 = CMP-0022957-5: RES, 26.1 k, 1%, 0.1 W, 0603; Manufacturer: Yageo; Power_W: 100mW; TempCo: 100 ppm/C; Value_Code: 26k1; Value: 26.1k; EIA_Code: E96; SizeX_mm: 1.6; SizeY_mm: 0.8; SizeZ_mm: 1; Value2: 0.1W; SizeArea_mm2: 1.28; AEC Qualified: N; VDC_V: 75V; AEC Category: Q200; SizeAreaWB_mm2: 4.68
R?#4 = CMP-0026742-1: RES, 6.80 k, 1%, 0.0625 W, 0402; Manufacturer: Yageo America; Power_W: 62.5mW; TempCo: 100 ppm/C; Value_Code: 6k80; U/M: EA; Value: 6.80k; Res_ohm: 6.8k; SizeX_mm: 1; SizeY_mm: 0.5; SizeZ_mm: 0.6; AEC Qualified: N; VDC_V: 50V; AEC Category: Q200
R?#5 = CMP-0026539-2: RES, 73.2 k, 1%, 0.063 W, AEC-Q200 Grade 0, 0402; Manufacturer: Vishay-Dale; Power_W: 63mW; TempCo: 100 ppm/C; Value_Code: 73k2; Value: 73.2k; EIA_Code: E96; SizeX_mm: 1; SizeY_mm: 0.5; SizeZ_mm: 0.6; Value2: 0.063W; AEC Qualified: Y; VDC_V: 50V; AEC Category: Q200; AEC Grade: 0
R?#6 = CMP-0026076-3: RES, 1.13 k, 1%, 0.063 W, AEC-Q200 Grade 0, 0402; Manufacturer: Vishay-Dale; Power_W: 63mW; TempCo: 100 ppm/C; Value_Code: 1k13; Value: 1.13k; EIA_Code: E96; SizeX_mm: 1; SizeY_mm: 0.5; SizeZ_mm: 0.6; Value2: 0.063W; AEC Qualified: Y; VDC_V: 50V; AEC Category: Q200; AEC Grade: 0
R?#7 = CMP-0026445-2: RES, 53.6 k, 1%, 0.063 W, AEC-Q200 Grade 0, 0402; Manufacturer: Vishay-Dale; Power_W: 63mW; TempCo: 100 ppm/C; Value_Code: 53k6; Value: 53.6k; EIA_Code: E96; SizeX_mm: 1; SizeY_mm: 0.5; SizeZ_mm: 0.6; Value2: 0.063W; AEC Qualified: Y; VDC_V: 50V; AEC Category: Q200; AEC Grade: 0
R?#8 = CMP-0026435-2: RES, 511 k, 1%, 0.063 W, AEC-Q200 Grade 0, 0402; Manufacturer: Vishay-Dale; Power_W: 63mW; TempCo: 100 ppm/C; Value: 511k; EIA_Code: E96; SizeX_mm: 1; SizeY_mm: 0.5; SizeZ_mm: 0.6; Value2: 0.063W; AEC Qualified: Y; VDC_V: 50V; AEC Category: Q200; AEC Grade: 0
R?#9 = CMP-0025988-3: RES, 127 k, 1%, 0.063 W, AEC-Q200 Grade 0, 0402; Manufacturer: Vishay-Dale; Power_W: 63mW; TempCo: 100 ppm/C; Value: 127k; EIA_Code: E96; SizeX_mm: 1; SizeY_mm: 0.5; SizeZ_mm: 0.6; Value2: 0.063W; AEC Qualified: Y; VDC_V: 50V; AEC Category: Q200; AEC Grade: 0
RT1 = CMP-0002523-3: Thermistor NTC, 47k ohm, 5%, 0603; Manufacturer: MuRata; TaMax_C: 125°C; SizeX_mm: 1.6; SizeY_mm: 0.8; TaMin_C: -40°C; Power_W: 100mW; SizeZ_mm: 1; SizeArea_mm2: 1.28; SizeAreaWB_mm2: 4.68; U/M: EA
T2 = CMP-0087465-1: Lm=200uH, Llk=5uH / P:S1:S2:A = 40:10:10:15; Manufacturer: Renco Electronics; AEC Qualified: No; SizeZ_mm: 0.66inch; DCR_ohm: 0.1; Ind_H: 110µH; Ns1toNp: 2.5:0.5:1:0.5:1
U3 = CMP-0033201-3: 0.5% Accuracy Low-Voltage Adjustable Precision Shunt Regulator, DCK0006A (SOT-SC70-6); Manufacturer: Texas Instruments; VO Adj(Max)(V): 6; Initial Accuracy @ 25/deg C(%): 0.5; Eco-Plan: Green (RoHS & no Sb/Br); Iout/Iz(Max)(mA): 15; Rating: Catalog; Temp Coeff(Max)(ppm/ degree C): 129; VO Adj(Min)(V): 1.24; Min Iz for Regulation(uA): 80; AEC Category: Q200; AEC Qualified: N; CompType: IC; SizeAreaWB_mm2: 9.3; SizeArea_mm2: 4.2; SizeX_mm: 2.1; SizeY_mm: 2.0; SizeZ_mm: 1.1
U4 = CMP-0860377-2: 4-A/6-A, Single-Channel Reinforced Isolation Gate Driver with High Noise Immunity, DWV0008A (SOIC-8); Manufacturer: Texas Instruments; SizeX_mm: 11.5; SizeArea_mm2: 67.275; SizeAreaWB_mm2: 105.975; CompType: IC; SizeZ_mm: 2.8; SizeY_mm: 5.85; AEC Category: Q200; AEC Qualified: N
U5 = CMP-0086087-1: UCC28781RTW, RTW0024B (WQFN-24); Manufacturer: Texas Instruments; SizeY_mm: 4; SizeZ_mm: 0.8; AEC Category: Q200; SizeArea_mm2: 16; CompType: IC; AEC Qualified: N; SizeAreaWB_mm2: 25
U6 = CMP-0087394-2: Optoisolator Transistor Output 5000Vrms 1 Channel 6-SO; Manufacturer: Toshiba; CTR (Max): 300%; CTR (Min): 100%; SizeZ_mm: 2.3mm
U7 = CMP-0066199-1: 2.5V Low Iq Adjustable Precision Shunt Regulator, DBZ0003A (SOT-23-3); Manufacturer: Texas Instruments; SizeArea_mm2: 7.5; SizeAreaWB_mm2: 14.0; SizeX_mm: 2.5; SizeY_mm: 3.0; SizeZ_mm: 1.12; CompType: IC; U/M: EA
